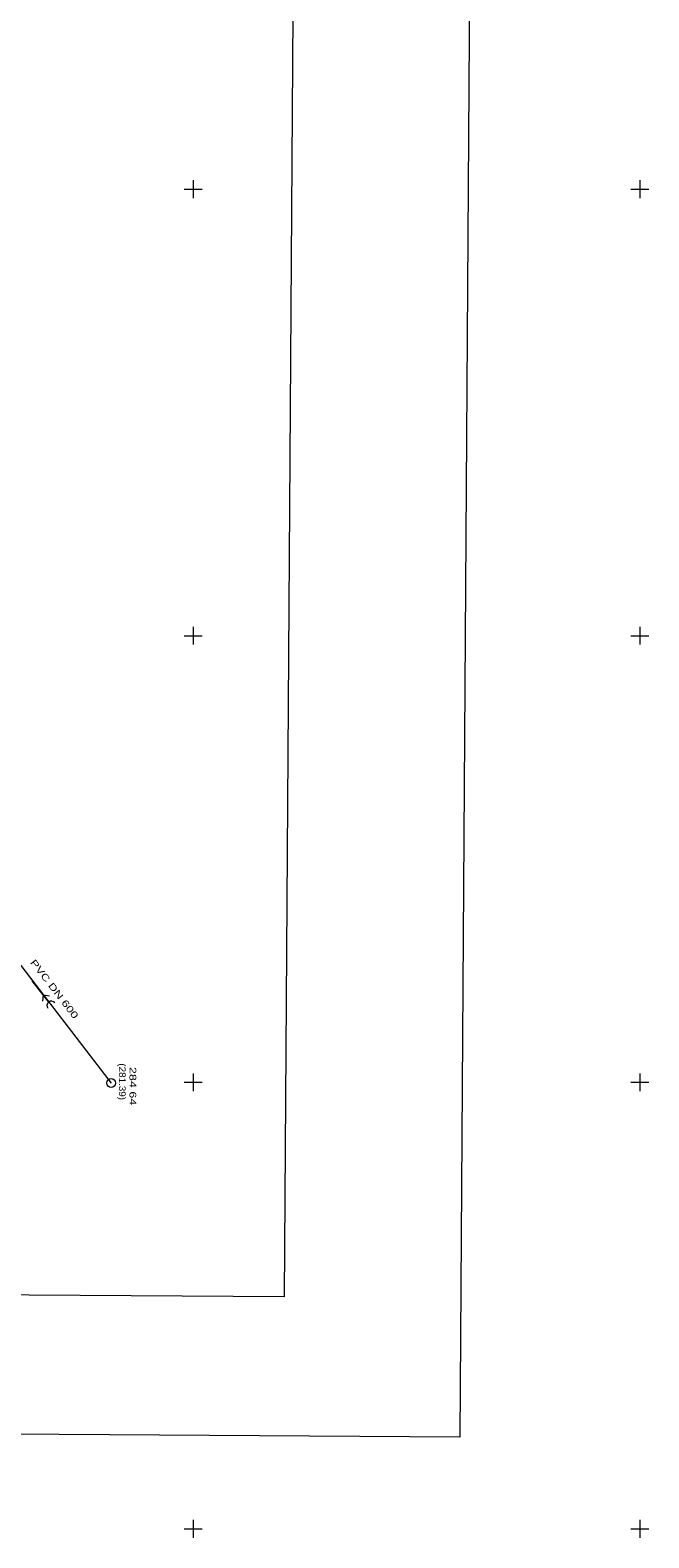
# Model space of a CAD drawing. Extents: x -649434 to -648798, y -1070102 to -1069235.
# Drawn here: x -648936.5 to -648798, y -1070102 to -1069764.4 of the extents above; entities that cross this region are included whole.
import ezdxf
from ezdxf.enums import TextEntityAlignment as Align

# ---------------------------------------------------------------- set-up
doc = ezdxf.new("R2010")
doc.units = 0
doc.header["$LTSCALE"] = 0.6
for name, color, linetype, lineweight in [('27', 7, 'Continuous', 13), ('36', 7, 'Continuous', 13), ('60', 7, 'Continuous', 13), ('61', 7, 'Continuous', 13), ('62', 7, 'Continuous', 13), ('63', 7, 'Continuous', 13)]:
    doc.layers.add(name, color=color, linetype=linetype, lineweight=lineweight)
doc.layers.add('3', color=7, linetype='Continuous')
doc.layers.add('4', color=7, linetype='Continuous')

msp = doc.modelspace()

# ---------------------------------------------------------------- linework, layer by layer
at = {"layer": '27'}
msp.add_circle((-648918.35, -1070000.17), 1, dxfattribs=at)
at = {"layer": '36'}
msp.add_lwpolyline([(-649256.3, -1069341.53), (-649240.28, -1069383.27), (-649221.1, -1069428.54), (-649201.15, -1069474.5), (-649181.05, -1069521.05), (-649161.63, -1069566.58), (-649142.48, -1069611.79), (-649122.43, -1069658.25), (-649109.25, -1069689.61), (-649102.53, -1069705.01), (-649082.85, -1069750.86), (-649061.09, -1069796.01), (-649037.43, -1069838.84), (-649009.95, -1069880.28), (-648980.08, -1069920.53), (-648948.81, -1069960.67), (-648918.35, -1070000.17)], dxfattribs=at)
at = {"layer": '60'}
for p, q in [((-648932.335, -1069982.034), (-648935.999, -1069977.283)), ((-648933.557, -1069980.45), (-648933.738, -1069981.853)), ((-648933.557, -1069980.45), (-648932.154, -1069980.631))]:
    msp.add_line(p, q, dxfattribs=at)
msp.add_arc((-648931.7248, -1069982.8258), 1, 37.63723, 217.63722, dxfattribs=at)
at = {"layer": '61'}
for p, q in [((-648902, -1069800), (-648898, -1069800)), ((-648900, -1069798), (-648900, -1069802)), ((-648802, -1069800), (-648798, -1069800)), ((-648800, -1069798), (-648800, -1069802)), ((-648900, -1069898), (-648900, -1069902)), ((-648800, -1069898), (-648800, -1069902)), ((-648902, -1069900), (-648898, -1069900)), ((-648802, -1069900), (-648798, -1069900)), ((-648900, -1069998), (-648900, -1070002)), ((-648800, -1069998), (-648800, -1070002)), ((-648902, -1070000), (-648898, -1070000)), ((-648802, -1070000), (-648798, -1070000)), ((-648902, -1070100), (-648898, -1070100)), ((-648900, -1070098), (-648900, -1070102)), ((-648802, -1070100), (-648798, -1070100)), ((-648800, -1070098), (-648800, -1070102))]:
    msp.add_line(p, q, dxfattribs=at)
at = {"layer": '62'}
msp.add_lwpolyline([(-648834.675, -1069239.477), (-648840.315, -1070079.458), (-649434.302, -1070075.471), (-649428.662, -1069235.487)], close=True, dxfattribs=at)
at = {"layer": '63'}
msp.add_lwpolyline([(-648876.771, -1069628.082), (-648879.591, -1070048.072), (-649176.584, -1070046.078), (-649173.764, -1069626.088)], close=True, dxfattribs=at)

# ---------------------------------------------------------------- texts
at = {"layer": '3', "width": 1.4}
msp.add_text('284 64 ', height=1.5, rotation=270, dxfattribs=at).set_placement((-648914.244, -1070001.243), align=Align.CENTER)
at = {"layer": '36', "width": 1.4}
msp.add_text('PVC DN 600', height=1.5, rotation=307.637, dxfattribs=at).set_placement((-648931.6517, -1069979.5675), align=Align.CENTER)
at = {"layer": '4', "width": 1.1}
msp.add_text('(281.39)', height=1.5, rotation=270, dxfattribs=at).set_placement((-648916.601, -1069999.8605), align=Align.CENTER)

doc.saveas('drawing.dxf')
